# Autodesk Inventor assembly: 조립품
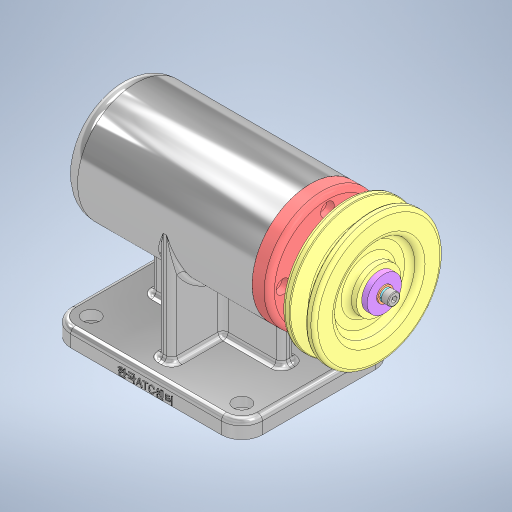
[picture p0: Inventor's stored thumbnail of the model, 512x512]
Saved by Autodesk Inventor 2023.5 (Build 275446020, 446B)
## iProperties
Created: 2026-08
Part Number: 조립품
Document SubType Name: Assembly
Designer: 1강의실14
Author: 1강의실14
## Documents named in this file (14)
- C:\Users\1강의실14\Desktop\760803V1009\조립품.iam
- C:\Users\1강의실14\Desktop\760803V1009\본체.ipt
- C:\Users\1강의실14\Desktop\760803V1009\6각 구멍붙이 볼트 M4x12\6각 구멍붙이 볼트 M4x12.ipt
- C:\Users\1강의실14\Desktop\760803V1009\V 벨트 풀리\V 벨트 풀리.ipt
- C:\Users\1강의실14\Desktop\760803V1009\깊은 홈 볼 베어링 6004\깊은 홈 볼 베어링 6004.ipt
- C:\Users\1강의실14\Desktop\760803V1009\스러스트 볼 베어링 51202\스러스트 볼 베어링 51202.ipt
- C:\Users\1강의실14\Desktop\760803V1009\스프링 와셔 M4\스프링 와셔 M4.ipt
- C:\Users\1강의실14\Desktop\760803V1009\어댑터 슬리브\어댑터 슬리브.ipt
- C:\Users\1강의실14\Desktop\760803V1009\엔드 캡\엔드 캡.ipt
- C:\Users\1강의실14\Desktop\760803V1009\오일 실 20 32 5\오일 실 20 32 5.ipt
- C:\Users\1강의실14\Desktop\760803V1009\축\축.ipt
- C:\Users\1강의실14\Desktop\760803V1009\커버\커버.ipt
- C:\Users\1강의실14\Desktop\760803V1009\평 와셔 M4\평 와셔 M4.ipt
- C:\Users\1강의실14\Desktop\760803V1009\평행 키 5x5x16\평행 키 5x5x16.ipt
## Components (3 placed, 2 different names)
1. 6각 구멍붙이 볼트 M4x12:1 — 각도:3
2. V 벨트 풀리:1
3. 6각 구멍붙이 볼트 M4x12:2 — 각도:11
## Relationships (2: Angle 2)
- 각도:3 [Angle]: 6각 구멍붙이 볼트 M4x12:1
- 각도:11 [Angle]: 6각 구멍붙이 볼트 M4x12:2
